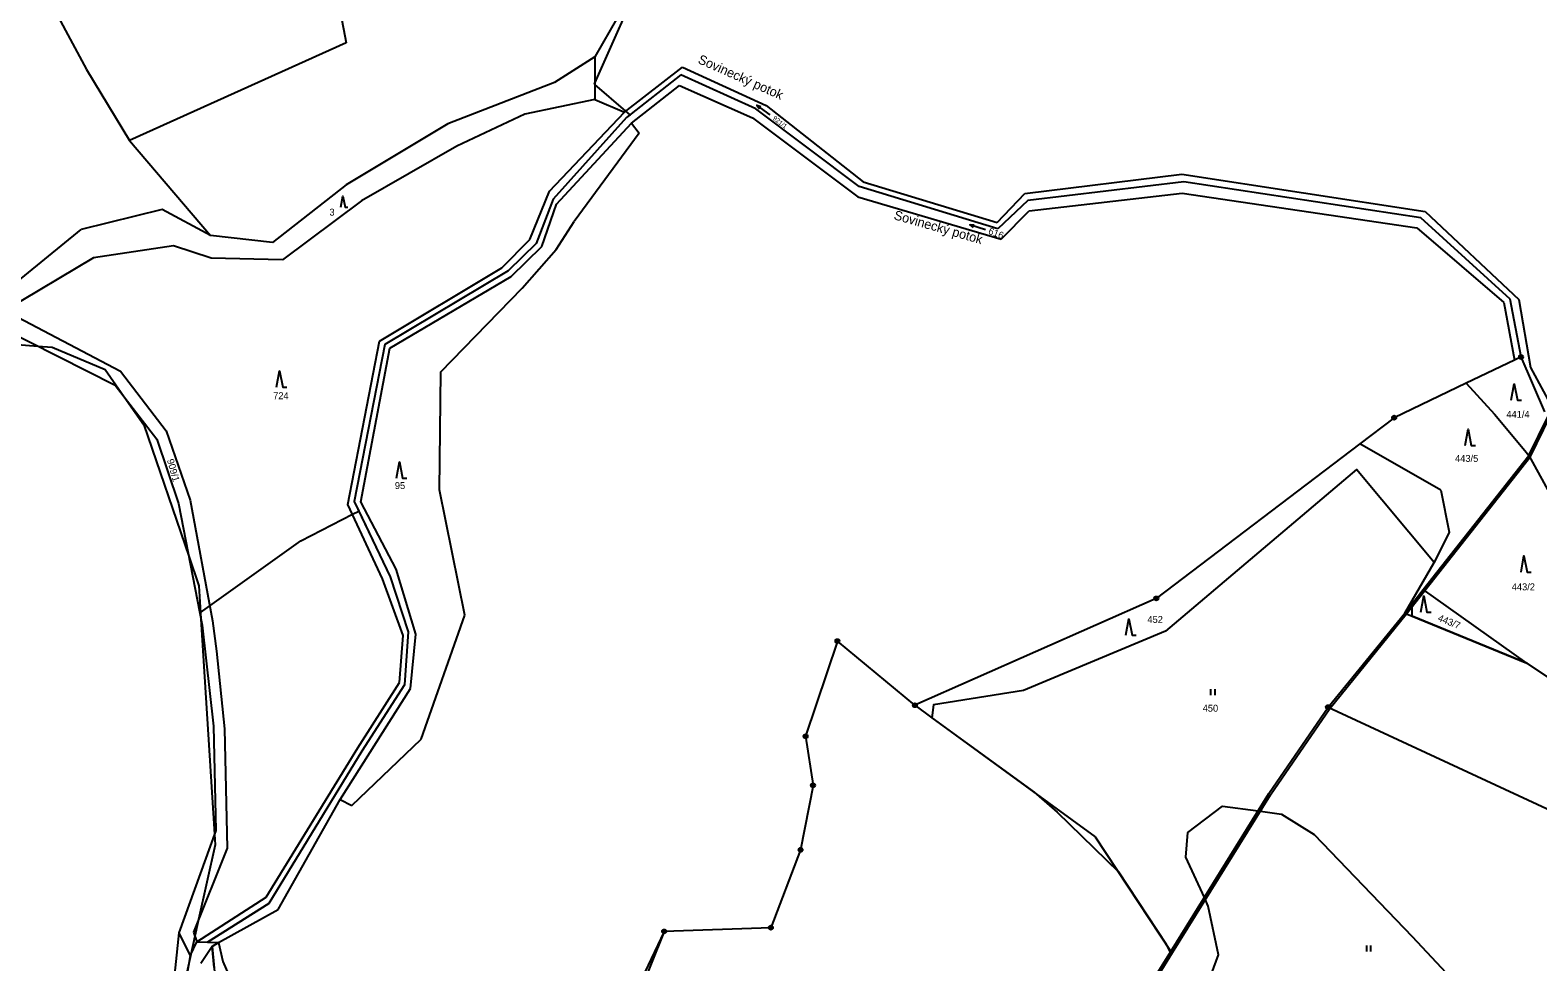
# Model space of a CAD drawing. Extents: x -547623 to -538651, y -1096714 to -1086522.
# Drawn here: x -544127.4 to -543757.7, y -1093688.2 to -1093459.8 of the extents above; entities that cross this region are included whole.
import ezdxf

# ---------------------------------------------------------------- set-up
doc = ezdxf.new("R2010")
doc.units = 0
for name, color, linetype in [('Vrstva 1', 7, 'Continuous'), ('Vrstva 25', 7, 'Continuous'), ('Vrstva 41', 7, 'Continuous'), ('Vrstva 50', 7, 'Continuous'), ('Vrstva 52', 7, 'Continuous'), ('Vrstva 62', 7, 'Continuous'), ('Vrstva 83', 7, 'Continuous'), ('Vrstva 86', 7, 'Continuous')]:
    doc.layers.add(name, color=color, linetype=linetype)

msp = doc.modelspace()

# ---------------------------------------------------------------- linework, layer by layer
at = {"layer": 'Vrstva 1'}
for points in [[(-544057.27, -1093424.31), (-544049.91, -1093462.91)], [(-543971.95, -1093436.83), (-543988.87, -1093466.28)], [(-544124.47, -1093449.02), (-544113.53, -1093469.45)], [(-544049.91, -1093462.91), (-544103, -1093486.8)], [(-543988.87, -1093466.28), (-543998.81, -1093472.63)], [(-543988.87, -1093466.28), (-543988.89, -1093476.8)], [(-544113.53, -1093469.45), (-544103, -1093486.8)], [(-543981.59, -1093479.9), (-543967.39, -1093468.85)], [(-543967.39, -1093468.85), (-543946.88, -1093478.21)], [(-543998.81, -1093472.63), (-544024.93, -1093482.74)], [(-543979.93, -1093482.58), (-543968.16, -1093473.32)], [(-543968.16, -1093473.32), (-543950.27, -1093481.28)], [(-543988.89, -1093476.8), (-544006.09, -1093480.4)], [(-543988.89, -1093476.8), (-543981.59, -1093479.9)], [(-543946.88, -1093478.21), (-543923.09, -1093496.99)], [(-544006.09, -1093480.4), (-544022.73, -1093488.18)], [(-544000.04, -1093499.27), (-543981.59, -1093479.9)], [(-543950.27, -1093481.28), (-543924.38, -1093500.61)], [(-544024.93, -1093482.74), (-544049.84, -1093497.69)], [(-543998.27, -1093502.41), (-543979.93, -1093482.58)], [(-543978.07, -1093485), (-543993.99, -1093506.66)], [(-543979.93, -1093482.58), (-543978.07, -1093485)], [(-544103, -1093486.8), (-544083.11, -1093510.13)], [(-544022.73, -1093488.18), (-544046.13, -1093501.64)], [(-543923.09, -1093496.99), (-543890.25, -1093506.89)], [(-543883.44, -1093499.81), (-543844.99, -1093495.11)], [(-543844.99, -1093495.11), (-543785.27, -1093504.21)], [(-544049.84, -1093497.69), (-544067.95, -1093511.85)], [(-544004.82, -1093511.12), (-544000.04, -1093499.27)], [(-543924.38, -1093500.61), (-543889.31, -1093511.03)], [(-543890.25, -1093506.89), (-543883.44, -1093499.81)], [(-543882.44, -1093504.06), (-543844.92, -1093499.75)], [(-543844.92, -1093499.75), (-543787.33, -1093508.21)], [(-544095, -1093503.7), (-544114.86, -1093508.66)], [(-544083.11, -1093510.13), (-544095, -1093503.7)], [(-544046.13, -1093501.64), (-544065.48, -1093516.08)], [(-544001.94, -1093512.83), (-543998.27, -1093502.41)], [(-543889.31, -1093511.03), (-543882.44, -1093504.06)], [(-543785.27, -1093504.21), (-543762.31, -1093525.8)], [(-543998.42, -1093513.58), (-543993.99, -1093506.66)], [(-543787.33, -1093508.21), (-543766, -1093526.57)], [(-544137.64, -1093527.2), (-544114.86, -1093508.66)], [(-544067.95, -1093511.85), (-544083.11, -1093510.13)], [(-544011.72, -1093518.07), (-544004.82, -1093511.12)], [(-544111.81, -1093515.6), (-544133.53, -1093528.52)], [(-544092.22, -1093512.61), (-544111.81, -1093515.6)], [(-544082.97, -1093515.64), (-544092.22, -1093512.61)], [(-544065.48, -1093516.08), (-544082.97, -1093515.64)], [(-544009.38, -1093520.17), (-544001.94, -1093512.83)], [(-544006.71, -1093523), (-543998.42, -1093513.58)], [(-544041.72, -1093536.01), (-544011.72, -1093518.07)], [(-544039.16, -1093537.76), (-544009.38, -1093520.17)], [(-544026.68, -1093543.51), (-544006.71, -1093523)], [(-543766, -1093526.57), (-543763.39, -1093540.67)], [(-543762.31, -1093525.8), (-543759.5, -1093542.44)], [(-544133.53, -1093528.52), (-544105.19, -1093543.38)], [(-544134.47, -1093532.65), (-544106.55, -1093546.84)], [(-544049.45, -1093576.08), (-544041.72, -1093536.01)], [(-544046.29, -1093575.37), (-544039.16, -1093537.76)], [(-544105.19, -1093543.38), (-544093.98, -1093558.02)], [(-544026.98, -1093572.45), (-544026.68, -1093543.51)], [(-543759.5, -1093542.44), (-543754.15, -1093552.27)], [(-544106.55, -1093546.84), (-544096.34, -1093560.05)], [(-543775.23, -1093546.33), (-543768.27, -1093553.89)], [(-543768.27, -1093553.89), (-543760.88, -1093562.83)], [(-543759.89, -1093564.02), (-543755.18, -1093554.37)], [(-544096.34, -1093560.05), (-544091, -1093575.83)], [(-544093.98, -1093558.02), (-544088.12, -1093575.02)], [(-543781.49, -1093572.56), (-543801.3, -1093561.15)], [(-543760.88, -1093562.83), (-543759.89, -1093564.02)], [(-543802.11, -1093567.52), (-543849, -1093607.11)], [(-543783.08, -1093590.28), (-543802.11, -1093567.52)], [(-543785.76, -1093596.88), (-543759.89, -1093564.02)], [(-543759.89, -1093564.02), (-543746.08, -1093589.26)], [(-544020.76, -1093603.16), (-544026.98, -1093572.45)], [(-543781.49, -1093572.56), (-543779.43, -1093582.85)], [(-544091, -1093575.83), (-544085.19, -1093605.67)], [(-544088.12, -1093575.02), (-544082.67, -1093604.55)], [(-544040.94, -1093594.26), (-544049.45, -1093576.08)], [(-544037.62, -1093591.88), (-544046.29, -1093575.37)], [(-543779.43, -1093582.85), (-543783.08, -1093590.28)], [(-544032.81, -1093607.85), (-544037.62, -1093591.88)], [(-543790.32, -1093602.67), (-543783.08, -1093590.28)], [(-544035.88, -1093608.15), (-544040.94, -1093594.26)], [(-543790.32, -1093602.67), (-543785.76, -1093596.88)], [(-543760.35, -1093614.98), (-543785.76, -1093596.88)], [(-544082.67, -1093604.55), (-544081.68, -1093612.06)], [(-544031.46, -1093633.57), (-544020.76, -1093603.16)], [(-543809.12, -1093625.74), (-543790.32, -1093602.67)], [(-543790.32, -1093602.67), (-543760.35, -1093614.98)], [(-544085.19, -1093605.67), (-544082.39, -1093630.38)], [(-544036.82, -1093619.74), (-544035.88, -1093608.15)], [(-544034.13, -1093621.16), (-544032.81, -1093607.85)], [(-543849, -1093607.11), (-543883.8, -1093621.66)], [(-544081.68, -1093612.06), (-544079.73, -1093631.04)], [(-543760.35, -1093614.98), (-543752.03, -1093620.49)], [(-544051.31, -1093648.38), (-544034.13, -1093621.16)], [(-544047.02, -1093635.75), (-544036.82, -1093619.74)], [(-543883.8, -1093621.66), (-543905.85, -1093625.2)], [(-543910.41, -1093625.29), (-543906.23, -1093628.33)], [(-543905.85, -1093625.2), (-543906.23, -1093628.33)], [(-543823.65, -1093646.95), (-543809.12, -1093625.74)], [(-543809.12, -1093625.74), (-543719.07, -1093667.54)], [(-544082.39, -1093630.38), (-544081.83, -1093656)], [(-543906.23, -1093628.33), (-543866.18, -1093657.51)], [(-544079.73, -1093631.04), (-544079.09, -1093660.32)], [(-544048.52, -1093649.88), (-544031.46, -1093633.57)], [(-544069.49, -1093672.31), (-544047.02, -1093635.75)], [(-544066.59, -1093675.37), (-544051.31, -1093648.38)], [(-544051.31, -1093648.38), (-544048.52, -1093649.88)], [(-543847.65, -1093685.64), (-543823.65, -1093646.95)], [(-544081.83, -1093656), (-544090.93, -1093681.11)], [(-543866.18, -1093657.51), (-543847.65, -1093685.64)], [(-544079.09, -1093660.32), (-544087.31, -1093680.91)], [(-544086.53, -1093683.25), (-544069.49, -1093672.31)], [(-544081.21, -1093683.45), (-544066.59, -1093675.37)], [(-544090.93, -1093681.11), (-544094.69, -1093716.96)], [(-544090.93, -1093681.11), (-544088.1, -1093686.68)], [(-544087.31, -1093680.91), (-544086.53, -1093683.25)], [(-543971.9, -1093680.72), (-543996.88, -1093742.97)], [(-544088.1, -1093686.68), (-544086.53, -1093683.25)], [(-544086.53, -1093683.25), (-544083.87, -1093683.35)], [(-544082.73, -1093684.4), (-544085.55, -1093688.57)], [(-544081.21, -1093683.45), (-544080.12, -1093688.07)], [(-543854.83, -1093697.21), (-543847.65, -1093685.64)], [(-544088.1, -1093686.68), (-544089, -1093691.95)], [(-544080.12, -1093688.07), (-544067.46, -1093717.13)]]:
    msp.add_lwpolyline(points, dxfattribs=at)
at = {"layer": 'Vrstva 25'}
for p, q in [((-543837.83, -1093622.85), (-543837.83, -1093621.35)), ((-543836.83, -1093622.85), (-543836.83, -1093621.35)), ((-543799.6, -1093685.65), (-543799.6, -1093684.15)), ((-543798.6, -1093685.65), (-543798.6, -1093684.15))]:
    msp.add_line(p, q, dxfattribs=at)
for points in [[(-543945.92, -1093480.52), (-543949.18, -1093478.16), (-543948.56, -1093479.02)], [(-543949.18, -1093478.16), (-543948.17, -1093478.48)], [(-544051.15, -1093503.19), (-544050.68, -1093500.51), (-544050.14, -1093503.19), (-544049.47, -1093503.19)], [(-543896.96, -1093507.5), (-543895.9, -1093507.48)], [(-543893.12, -1093508.7), (-543896.96, -1093507.5), (-543896.1, -1093508.12)], [(-544066.94, -1093547.27), (-544066.24, -1093543.27), (-544065.44, -1093547.27), (-544064.44, -1093547.27)], [(-543764.2, -1093550.51), (-543763.5, -1093546.51), (-543762.7, -1093550.51), (-543761.7, -1093550.51)], [(-543775.49, -1093561.57), (-543774.79, -1093557.57), (-543773.99, -1093561.57), (-543772.99, -1093561.57)], [(-544037.54, -1093569.58), (-544036.84, -1093565.58), (-544036.04, -1093569.58), (-544035.04, -1093569.58)], [(-543761.8, -1093592.66), (-543761.1, -1093588.66), (-543760.3, -1093592.66), (-543759.3, -1093592.66)], [(-543786.36, -1093602.46), (-543785.66, -1093598.46), (-543784.86, -1093602.46), (-543783.86, -1093602.46)], [(-543858.67, -1093608.09), (-543857.97, -1093604.09), (-543857.17, -1093608.09), (-543856.17, -1093608.09)]]:
    msp.add_lwpolyline(points, dxfattribs=at)
at = {"layer": 'Vrstva 41'}
for points in [[(-543967.8, -1093470.7), (-543981.1, -1093481.18)], [(-543967.8, -1093470.7), (-543981.1, -1093481.18)], [(-543949.41, -1093479.04), (-543967.8, -1093470.7)], [(-543949.41, -1093479.04), (-543967.8, -1093470.7)], [(-543981.1, -1093481.18), (-543999.09, -1093501.24)], [(-543981.1, -1093481.18), (-543999.09, -1093501.24)], [(-543924.11, -1093498.09), (-543949.41, -1093479.04)], [(-543924.11, -1093498.09), (-543949.41, -1093479.04)], [(-543844.46, -1093496.98), (-543882.71, -1093501.51)], [(-543844.46, -1093496.98), (-543882.71, -1093501.51)], [(-543786.38, -1093505.77), (-543844.46, -1093496.98)], [(-543786.38, -1093505.77), (-543844.46, -1093496.98)], [(-543890.07, -1093508.45), (-543924.11, -1093498.09)], [(-543890.07, -1093508.45), (-543924.11, -1093498.09)], [(-543999.09, -1093501.24), (-544003.3, -1093512.09)], [(-543999.09, -1093501.24), (-544003.3, -1093512.09)], [(-543882.71, -1093501.51), (-543890.07, -1093508.45)], [(-543882.71, -1093501.51), (-543890.07, -1093508.45)], [(-543764.5, -1093525.7), (-543786.38, -1093505.77)], [(-543764.5, -1093525.7), (-543786.38, -1093505.77)], [(-544003.3, -1093512.09), (-544010.17, -1093518.81)], [(-544003.3, -1093512.09), (-544010.17, -1093518.81)], [(-544010.17, -1093518.81), (-544040.41, -1093536.83)], [(-544010.17, -1093518.81), (-544040.41, -1093536.83)], [(-543761.78, -1093539.9), (-543764.5, -1093525.7)], [(-543761.78, -1093539.9), (-543764.5, -1093525.7)], [(-544040.41, -1093536.83), (-544047.91, -1093575.32)], [(-544040.41, -1093536.83), (-544047.91, -1093575.32)], [(-543763.39, -1093540.67), (-543775.23, -1093546.33)], [(-543763.39, -1093540.67), (-543775.23, -1093546.33)], [(-543761.78, -1093539.9), (-543763.39, -1093540.67)], [(-543761.78, -1093539.9), (-543763.39, -1093540.67)], [(-543755.98, -1093553.33), (-543761.78, -1093539.9)], [(-543755.98, -1093553.33), (-543761.78, -1093539.9)], [(-543775.23, -1093546.33), (-543792.91, -1093554.78)], [(-543775.23, -1093546.33), (-543792.91, -1093554.78)], [(-543792.91, -1093554.78), (-543801.3, -1093561.15)], [(-543792.91, -1093554.78), (-543801.3, -1093561.15)], [(-543801.3, -1093561.15), (-543851.23, -1093599.08)], [(-543801.3, -1093561.15), (-543851.23, -1093599.08)], [(-544047.91, -1093575.32), (-544039.09, -1093593.78)], [(-544047.91, -1093575.32), (-544039.09, -1093593.78)], [(-544039.09, -1093593.78), (-544034.68, -1093607.25)], [(-544039.09, -1093593.78), (-544034.68, -1093607.25)], [(-543851.23, -1093599.08), (-543910.41, -1093625.29)], [(-543851.23, -1093599.08), (-543910.41, -1093625.29)], [(-544034.68, -1093607.25), (-544035.54, -1093620.28)], [(-544034.68, -1093607.25), (-544035.54, -1093620.28)], [(-543929.42, -1093609.54), (-543937.23, -1093632.89)], [(-543929.42, -1093609.54), (-543937.23, -1093632.89)], [(-543910.41, -1093625.29), (-543929.42, -1093609.54)], [(-543910.41, -1093625.29), (-543929.42, -1093609.54)], [(-544035.54, -1093620.28), (-544046.07, -1093636.55)], [(-544035.54, -1093620.28), (-544046.07, -1093636.55)], [(-543937.23, -1093632.89), (-543935.4, -1093644.94)], [(-543937.23, -1093632.89), (-543935.4, -1093644.94)], [(-544046.07, -1093636.55), (-544068.82, -1093673.86)], [(-544046.07, -1093636.55), (-544068.82, -1093673.86)], [(-543935.4, -1093644.94), (-543938.46, -1093660.72)], [(-543935.4, -1093644.94), (-543938.46, -1093660.72)], [(-543938.46, -1093660.72), (-543945.75, -1093679.82)], [(-543938.46, -1093660.72), (-543945.75, -1093679.82)], [(-544083.87, -1093683.35), (-544068.82, -1093673.86)], [(-544083.87, -1093683.35), (-544068.82, -1093673.86)], [(-543971.9, -1093680.72), (-544000.42, -1093740.74)], [(-543971.9, -1093680.72), (-544000.42, -1093740.74)], [(-543945.75, -1093679.82), (-543971.9, -1093680.72)], [(-543945.75, -1093679.82), (-543971.9, -1093680.72)], [(-544083.87, -1093683.35), (-544081.21, -1093683.45)], [(-544083.87, -1093683.35), (-544081.21, -1093683.45)], [(-544082.73, -1093684.4), (-544081.21, -1093683.45)], [(-544082.73, -1093684.4), (-544081.21, -1093683.45)], [(-544082.25, -1093689.58), (-544082.73, -1093684.4)], [(-544082.25, -1093689.58), (-544082.73, -1093684.4)]]:
    msp.add_lwpolyline(points, dxfattribs=at)
at = {"layer": 'Vrstva 52'}
for points in [[(-543980.28, -1093480.53), (-543981.29, -1093479.66), (-543988.88, -1093473.1), (-543989, -1093473), (-543988.88, -1093472.73), (-543976.4, -1093444.57)], [(-543980.28, -1093480.53), (-543981.1, -1093481.18), (-543999.09, -1093501.24), (-544003.3, -1093512.09), (-544010.17, -1093518.81), (-544040.41, -1093536.83), (-544047.91, -1093575.32), (-544046.78, -1093577.68)], [(-544172, -1093533.5), (-544125.47, -1093537.22), (-544122, -1093537.5), (-544109, -1093543), (-544103.73, -1093550.48), (-544099.5, -1093556.5), (-544088.49, -1093588.71), (-544086, -1093596), (-544085.59, -1093602.51)], [(-543752.03, -1093620.49), (-543760.35, -1093614.98), (-543788.5, -1093603.42), (-543788.5, -1093600.36), (-543788.5, -1093599.56), (-543783.08, -1093590.28), (-543802.11, -1093567.52), (-543849, -1093607.11), (-543883.8, -1093621.66), (-543905.85, -1093625.2), (-543906.23, -1093628.33), (-543881.21, -1093646.56), (-543875.5, -1093651.5), (-543860.5, -1093666.14), (-543848.81, -1093683.88), (-543847.81, -1093685.89), (-543854.83, -1093697.21), (-543862.54, -1093709.63), (-543901.43, -1093791.17), (-543906.85, -1093814.42), (-543929.56, -1093847.98)], [(-544085.59, -1093602.51), (-544083.34, -1093600.91), (-544061, -1093585), (-544048.33, -1093578.47), (-544046.78, -1093577.68)], [(-544046.78, -1093577.68), (-544039.09, -1093593.78), (-544034.68, -1093607.25), (-544035.54, -1093620.28), (-544046.07, -1093636.55), (-544068.82, -1093673.86), (-544083.87, -1093683.35), (-544081.21, -1093683.45), (-544082.73, -1093684.4), (-544081.32, -1093699.49), (-544077.96, -1093705.76), (-544077.44, -1093706.72), (-544077.9, -1093707.39), (-544082.34, -1093713.83), (-544082.98, -1093729.5), (-544083.17, -1093734.21)], [(-544085.59, -1093602.51), (-544085.49, -1093604.15), (-544082.16, -1093656.92), (-544082, -1093659.5), (-544086.06, -1093677.79), (-544086.98, -1093681.9), (-544087.98, -1093686.43), (-544088.3, -1093687.85), (-544094.62, -1093716.29), (-544094.77, -1093716.95), (-544095, -1093718), (-544102, -1093718), (-544104, -1093723), (-544124.5, -1093738.5), (-544137, -1093758)], [(-543944, -1093922.5), (-543896.5, -1093871), (-543879, -1093839.5), (-543864.5, -1093803), (-543860.5, -1093780.5), (-543856, -1093741), (-543845.02, -1093711.07), (-543836, -1093686.5), (-543838.5, -1093674.5), (-543839.45, -1093672.42), (-543844, -1093662.5), (-543843.5, -1093656.5), (-543835, -1093650), (-543826.29, -1093651.2), (-543820.5, -1093652), (-543812.5, -1093657), (-543788.5, -1093682), (-543766, -1093706), (-543763.21, -1093707.8), (-543750, -1093716.29)]]:
    msp.add_lwpolyline(points, dxfattribs=at)
at = {"layer": 'Vrstva 62'}
msp.add_lwpolyline([(-543666.67, -1093961.99), (-543749.45, -1093845.6), (-543803.39, -1093769.02), (-543854.23, -1093697.19), (-543847.22, -1093685.9), (-543823.23, -1093647.22), (-543808.71, -1093626.04), (-543789.93, -1093602.98), (-543785.36, -1093597.18), (-543759.46, -1093564.28), (-543754.73, -1093554.59), (-543753.76, -1093552.62), (-543751.53, -1093551.33), (-543748.48, -1093549.35), (-543744.68, -1093546.88), (-543703.85, -1093520.37), (-543687.82, -1093508), (-543681.44, -1093502.02), (-543677.2, -1093498.03)], dxfattribs=at)
at = {"layer": 'Vrstva 83'}
for centre, radius in [((-543761.78, -1093539.9), 0.5), ((-543761.78, -1093539.9), 0.1), ((-543792.91, -1093554.78), 0.5), ((-543792.91, -1093554.78), 0.1), ((-543851.23, -1093599.08), 0.5), ((-543851.23, -1093599.08), 0.1), ((-543929.42, -1093609.54), 0.5), ((-543929.42, -1093609.54), 0.1), ((-543910.41, -1093625.29), 0.5), ((-543910.41, -1093625.29), 0.1), ((-543809.12, -1093625.74), 0.5), ((-543809.12, -1093625.74), 0.1), ((-543937.23, -1093632.89), 0.5), ((-543937.23, -1093632.89), 0.1), ((-543935.4, -1093644.94), 0.5), ((-543935.4, -1093644.94), 0.1), ((-543938.46, -1093660.72), 0.5), ((-543938.46, -1093660.72), 0.1), ((-543971.9, -1093680.72), 0.5), ((-543971.9, -1093680.72), 0.1), ((-543945.75, -1093679.82), 0.5), ((-543945.75, -1093679.82), 0.1)]:
    msp.add_circle(centre, radius, dxfattribs=at)

# ---------------------------------------------------------------- texts
at = {"layer": 'Vrstva 50'}
for rotation, p in [(336.0368, (-543963.82, -1093467.77)), (344.0389, (-543915.74, -1093506.1))]:
    msp.add_text('Sovinecký potok', height=2.3, rotation=rotation, dxfattribs=at).set_placement(p)
at = {"layer": 'Vrstva 86'}
for s, height, rotation, p in [('921/1', 1.14, 322.0379, (-543945.4, -1093481.58)), ('616', 1.7, 339.2277, (-543892.58, -1093509.68)), ('909/1', 1.7, 285.5788, (-544093.84, -1093565.15)), ('443/7', 1.7, 337.7526, (-543782.35, -1093604.51))]:
    msp.add_text(s, height=height, rotation=rotation, dxfattribs=at).set_placement(p)
for s, p in [('3', (-544053.98, -1093505.24)), ('724', (-544067.78, -1093550.24)), ('441/4', (-543765.39, -1093554.8)), ('443/5', (-543777.97, -1093565.61)), ('95', (-544037.94, -1093572.28)), ('443/2', (-543764.07, -1093597.11)), ('452', (-543853.41, -1093605.1)), ('450', (-543839.86, -1093626.86))]:
    msp.add_text(s, height=1.7, dxfattribs=at).set_placement(p)

doc.saveas('drawing.dxf')
